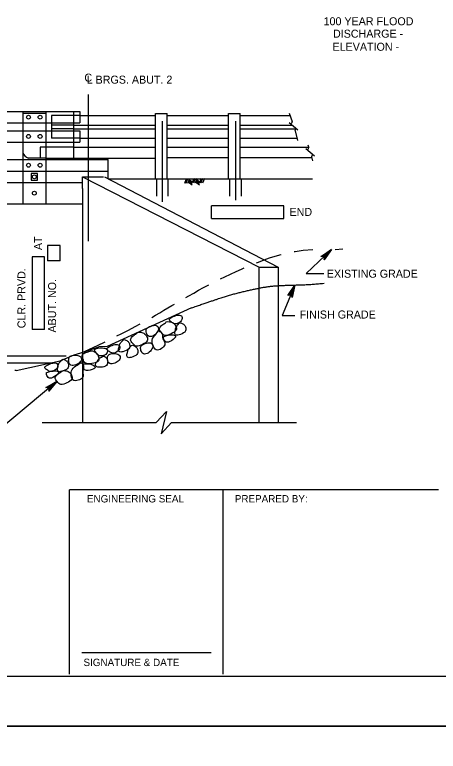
# Model space of a CAD drawing. Extents: x -8 to 75, y -110 to 0.
# Drawn here: x 11.66 to 18.01, y -44.38 to -33.33 of the extents above; entities that cross this region are included whole.
import ezdxf

# ---------------------------------------------------------------- set-up
doc = ezdxf.new("R2010")
doc.units = 0
for name, color, linetype in [('1', 7, 'Continuous'), ('10', 7, 'Continuous'), ('3', 7, 'Continuous'), ('4', 7, 'Continuous'), ('63', 7, 'Continuous'), ('8', 7, 'Continuous')]:
    doc.layers.add(name, color=color, linetype=linetype)

# ---------------------------------------------------------------- blocks, each defined once
blk = doc.blocks.new('F10000')
at = {"layer": '63'}
blk.add_lwpolyline([(-0.03125, -0.03125), (0.03125, -0.03125), (0.03125, 0.03125), (-0.03125, 0.03125)], close=True, dxfattribs=at)

msp = doc.modelspace()

# ---------------------------------------------------------------- linework, layer by layer
at = {"layer": '1'}
msp.add_lwpolyline([(1.75, -43.25), (33.25, -43.25), (33.25, -22.75), (1.75, -22.75)], close=True, dxfattribs=at)
at = {"layer": '3'}
for p, q in [((5.56, -34.783), (12.637, -34.783)), ((11.781, -34.783), (11.781, -36.167)), ((11.781, -34.812), (12.127, -34.812)), ((12.127, -34.783), (12.127, -36.167)), ((12.637, -34.844), (12.213, -34.844)), ((12.213, -34.844), (12.213, -35.184)), ((12.542, -34.783), (12.542, -34.956)), ((12.637, -34.783), (12.637, -34.956)), ((12.637, -34.844), (13.77, -34.844)), ((13.77, -34.814), (13.943, -34.814)), ((13.77, -35.792), (13.77, -34.814)), ((13.943, -35.792), (13.943, -34.814)), ((13.943, -34.846), (14.866, -34.846)), ((14.866, -34.817), (15.039, -34.817)), ((14.866, -35.792), (14.866, -34.817)), ((15.039, -35.792), (15.039, -34.817)), ((15.039, -34.846), (15.787, -34.846)), ((15.775, -34.809), (15.816, -34.936)), ((10.223, -34.956), (11.781, -34.956)), ((11.781, -34.956), (12.127, -34.956)), ((12.127, -34.956), (12.637, -34.956)), ((12.542, -34.99), (12.213, -34.99)), ((12.542, -34.956), (12.542, -35.072)), ((12.542, -34.99), (13.77, -34.99)), ((13.871, -34.927), (13.871, -36.138)), ((13.943, -34.99), (14.866, -34.99)), ((14.967, -34.927), (14.967, -36.113)), ((15.039, -34.99), (15.82, -34.99)), ((15.773, -34.951), (15.904, -35.061)), ((10.223, -35.072), (11.781, -35.072)), ((11.781, -35.072), (12.127, -35.072)), ((12.127, -35.072), (12.637, -35.072)), ((12.542, -35.042), (12.213, -35.042)), ((12.542, -35.042), (13.77, -35.042)), ((12.542, -35.072), (12.542, -35.245)), ((12.637, -35.072), (12.637, -35.245)), ((13.943, -35.042), (14.866, -35.042)), ((15.039, -35.042), (15.882, -35.042)), ((15.861, -35.074), (15.897, -35.219)), ((12.637, -35.184), (12.213, -35.184)), ((12.637, -35.184), (13.77, -35.184)), ((13.943, -35.184), (14.866, -35.184)), ((15.039, -35.184), (15.888, -35.184)), ((10.223, -35.245), (11.781, -35.245)), ((11.781, -35.245), (12.127, -35.245)), ((12.542, -35.32), (12.04, -35.32)), ((12.04, -35.32), (12.04, -35.483)), ((12.127, -35.245), (12.637, -35.245)), ((12.542, -35.245), (12.542, -35.483)), ((12.542, -35.32), (13.77, -35.32)), ((13.943, -35.32), (14.866, -35.32)), ((15.039, -35.32), (16.064, -35.32)), ((16.053, -35.285), (16.066, -35.324)), ((16.023, -35.34), (16.154, -35.45)), ((10.223, -35.504), (11.781, -35.504)), ((11.781, -35.504), (12.127, -35.504)), ((12.127, -35.483), (11.863, -35.483)), ((12.126, -35.483), (13.77, -35.483)), ((12.127, -35.504), (13.059, -35.504)), ((13.059, -35.792), (13.059, -35.504)), ((14.866, -35.478), (13.943, -35.478)), ((16.114, -35.478), (15.039, -35.478)), ((16.11, -35.463), (16.125, -35.523)), ((10.223, -35.677), (11.781, -35.677)), ((11.781, -35.677), (12.127, -35.677)), ((12.127, -35.677), (13.059, -35.677)), ((12.675, -35.764), (15.323, -37.119)), ((12.675, -35.937), (12.675, -35.764)), ((12.675, -35.764), (12.992, -35.764)), ((13.003, -35.764), (15.608, -37.119)), ((10.223, -35.85), (11.781, -35.85)), ((11.781, -35.85), (12.127, -35.85)), ((12.127, -35.85), (12.675, -35.85)), ((13.059, -35.792), (16.125, -35.792)), ((13.784, -35.792), (13.784, -36.052)), ((13.957, -35.792), (13.957, -36.052)), ((14.229, -35.792), (14.203, -35.863)), ((14.251, -35.792), (14.225, -35.862)), ((14.277, -35.792), (14.25, -35.862)), ((14.258, -35.84), (14.318, -35.882)), ((14.265, -35.822), (14.317, -35.858)), ((14.271, -35.805), (14.323, -35.841)), ((14.342, -35.792), (14.316, -35.861)), ((14.364, -35.791), (14.338, -35.86)), ((14.389, -35.791), (14.363, -35.86)), ((14.371, -35.84), (14.431, -35.882)), ((14.377, -35.822), (14.429, -35.858)), ((14.384, -35.805), (14.435, -35.841)), ((14.454, -35.791), (14.428, -35.86)), ((14.476, -35.791), (14.45, -35.86)), ((14.502, -35.791), (14.476, -35.86)), ((14.88, -35.792), (14.88, -36.052)), ((15.053, -35.792), (15.053, -36.052)), ((12.675, -35.937), (12.675, -38.397)), ((5.523, -36.167), (12.675, -36.167)), ((16.409, -36.855), (16.03, -37.212)), ((15.323, -37.119), (15.608, -37.119)), ((15.323, -37.433), (15.323, -37.119)), ((15.608, -37.119), (15.608, -37.397)), ((16.03, -37.212), (16.294, -37.212)), ((15.608, -37.397), (15.608, -39.448)), ((15.859, -37.386), (15.668, -37.842)), ((15.323, -39.448), (15.323, -37.433)), ((14.309, -37.728), (13.045, -38.308)), ((15.668, -37.842), (15.859, -37.842)), ((13.045, -38.308), (12.919, -38.311)), ((12.675, -38.397), (12.675, -39.448)), ((5.777, -38.552), (12.207, -38.552)), ((13.779, -39.448), (13.933, -39.281)), ((13.933, -39.281), (13.856, -39.614)), ((12.072, -39.448), (13.779, -39.448)), ((13.856, -39.614), (14.01, -39.448)), ((14.01, -39.448), (15.883, -39.448))]:
    msp.add_line(p, q, dxfattribs=at)
for points in [[(16.307, -36.924), (16.334, -36.952), (16.407, -36.857)], [(15.795, -37.488), (15.831, -37.503), (15.859, -37.386)]]:
    msp.add_lwpolyline(points, close=True, dxfattribs=at)
for centre in [(11.867, -34.87), (12.04, -34.87), (11.867, -35.158), (12.04, -35.158), (11.867, -35.59), (12.04, -35.59), (11.954, -35.763), (11.954, -36.008)]:
    msp.add_circle(centre, 0.0288, dxfattribs=at)
for centre, radius, start, end in [((15.796, -34.942), 0.0213, 227.8504, 17.8504), ((15.881, -35.07), 0.0213, 49.9832, 192.5218), ((15.882, -35.07), 0.0213, 49.9832, 49.9972), ((16.045, -35.331), 0.0213, 227.8504, 17.8504), ((11.896, -35.37), 0.118, 193.1962, 254.1617), ((16.131, -35.458), 0.0213, 49.9832, 192.5218), ((16.131, -35.458), 0.0213, 49.9832, 49.9972), ((11.66, -39.127), 0.459, 87.4213, 90)]:
    msp.add_arc(centre, radius, start, end, dxfattribs=at)
for points, degree in [([(14.309, -37.728), (14.62, -37.621), (14.906, -37.528), (15.192, -37.458), (15.462, -37.405), (15.716, -37.388), (16.057, -37.382), (16.296, -37.359)], 2), ([(13.983, -37.921), (13.993, -37.932), (14.028, -37.954), (14.072, -37.98), (14.151, -37.942), (14.182, -37.865), (14.138, -37.829), (14.057, -37.846), (13.97, -37.892), (13.974, -37.911), (13.983, -37.921)], 3), ([(13.927, -37.944), (13.925, -37.947), (13.912, -37.959), (13.848, -37.995), (13.816, -38.053), (13.856, -38.094), (13.904, -38.16), (14.008, -38.12), (14.096, -38.063), (14.074, -37.999), (14.043, -37.954), (13.979, -37.93), (13.925, -37.938), (13.929, -37.94), (13.927, -37.944)], 3), ([(14.068, -38.061), (14.066, -38.073), (14.054, -38.088), (14.06, -38.137), (14.113, -38.144), (14.229, -38.094), (14.225, -38.023), (14.205, -37.98), (14.154, -37.951), (14.128, -37.95), (14.116, -37.974), (14.069, -38.016), (14.071, -38.049), (14.068, -38.061)], 3), ([(13.638, -38.037), (13.627, -38.052), (13.628, -38.086), (13.653, -38.159), (13.727, -38.164), (13.797, -38.099), (13.825, -38.034), (13.786, -37.98), (13.695, -37.997), (13.649, -38.022), (13.638, -38.037)], 3), ([(13.811, -38.076), (13.805, -38.08), (13.801, -38.098), (13.71, -38.19), (13.72, -38.279), (13.776, -38.382), (13.864, -38.342), (13.921, -38.281), (13.902, -38.227), (13.872, -38.186), (13.877, -38.112), (13.834, -38.076), (13.816, -38.072), (13.811, -38.076)], 3), ([(13.496, -38.103), (13.494, -38.106), (13.48, -38.118), (13.417, -38.154), (13.385, -38.212), (13.425, -38.254), (13.473, -38.319), (13.577, -38.279), (13.665, -38.222), (13.643, -38.158), (13.612, -38.113), (13.548, -38.089), (13.494, -38.097), (13.498, -38.1), (13.496, -38.103)], 3), ([(13.909, -38.153), (13.892, -38.158), (13.88, -38.163), (13.908, -38.245), (13.977, -38.252), (14.102, -38.153), (14.028, -38.132), (13.98, -38.128), (13.925, -38.147), (13.909, -38.153)], 3), ([(13.048, -38.361), (13.058, -38.371), (13.092, -38.393), (13.136, -38.419), (13.216, -38.381), (13.246, -38.304), (13.203, -38.268), (13.122, -38.286), (13.035, -38.331), (13.038, -38.35), (13.048, -38.361)], 3), ([(13.227, -38.313), (13.225, -38.325), (13.213, -38.34), (13.219, -38.389), (13.272, -38.395), (13.388, -38.346), (13.384, -38.275), (13.364, -38.231), (13.313, -38.203), (13.287, -38.202), (13.275, -38.226), (13.229, -38.267), (13.23, -38.301), (13.227, -38.313)], 3), ([(13.35, -38.398), (13.347, -38.41), (13.335, -38.425), (13.341, -38.474), (13.395, -38.48), (13.511, -38.43), (13.507, -38.36), (13.487, -38.316), (13.436, -38.288), (13.41, -38.286), (13.398, -38.311), (13.351, -38.352), (13.353, -38.386), (13.35, -38.398)], 3), ([(13.554, -38.299), (13.543, -38.314), (13.544, -38.348), (13.569, -38.421), (13.643, -38.426), (13.713, -38.361), (13.741, -38.296), (13.702, -38.242), (13.611, -38.259), (13.565, -38.284), (13.554, -38.299)], 3), ([(12.799, -38.374), (12.796, -38.376), (12.78, -38.383), (12.708, -38.397), (12.659, -38.44), (12.684, -38.493), (12.708, -38.57), (12.818, -38.566), (12.921, -38.541), (12.921, -38.474), (12.906, -38.421), (12.853, -38.377), (12.799, -38.368), (12.803, -38.371), (12.799, -38.374)], 3), ([(12.86, -38.371), (12.866, -38.384), (12.891, -38.416), (12.925, -38.455), (13.012, -38.445), (13.066, -38.382), (13.036, -38.333), (12.954, -38.324), (12.857, -38.339), (12.854, -38.358), (12.86, -38.371)], 3), ([(13.073, -38.429), (13.057, -38.439), (13.048, -38.471), (13.048, -38.548), (13.116, -38.577), (13.203, -38.539), (13.251, -38.486), (13.231, -38.423), (13.14, -38.409), (13.088, -38.418), (13.073, -38.429)], 3), ([(12.31, -38.608), (12.307, -38.62), (12.295, -38.635), (12.301, -38.684), (12.355, -38.69), (12.471, -38.64), (12.467, -38.57), (12.447, -38.526), (12.396, -38.498), (12.37, -38.497), (12.358, -38.521), (12.311, -38.562), (12.313, -38.596), (12.31, -38.608)], 3), ([(12.492, -38.453), (12.477, -38.463), (12.467, -38.495), (12.467, -38.573), (12.535, -38.602), (12.622, -38.563), (12.67, -38.51), (12.651, -38.447), (12.559, -38.433), (12.507, -38.442), (12.492, -38.453)], 3), ([(12.895, -38.531), (12.888, -38.541), (12.872, -38.551), (12.862, -38.599), (12.911, -38.623), (13.036, -38.614), (13.056, -38.546), (13.051, -38.498), (13.012, -38.455), (12.988, -38.445), (12.968, -38.464), (12.911, -38.488), (12.901, -38.52), (12.895, -38.531)], 3), ([(12.118, -38.637), (12.128, -38.647), (12.162, -38.669), (12.207, -38.695), (12.286, -38.658), (12.316, -38.581), (12.273, -38.544), (12.192, -38.562), (12.105, -38.608), (12.108, -38.627), (12.118, -38.637)], 3), ([(12.65, -38.551), (12.644, -38.552), (12.633, -38.568), (12.518, -38.626), (12.499, -38.713), (12.518, -38.829), (12.614, -38.819), (12.687, -38.781), (12.687, -38.723), (12.672, -38.675), (12.701, -38.607), (12.672, -38.559), (12.656, -38.549), (12.65, -38.551)], 3), ([(12.714, -38.565), (12.696, -38.565), (12.684, -38.565), (12.684, -38.652), (12.746, -38.681), (12.896, -38.628), (12.834, -38.585), (12.79, -38.565), (12.732, -38.565), (12.714, -38.565)], 3), ([(12.156, -38.692), (12.139, -38.697), (12.127, -38.702), (12.155, -38.784), (12.224, -38.791), (12.348, -38.692), (12.275, -38.671), (12.227, -38.667), (12.172, -38.686), (12.156, -38.692)], 3), ([(12.365, -38.679), (12.363, -38.682), (12.349, -38.694), (12.286, -38.73), (12.254, -38.788), (12.294, -38.829), (12.342, -38.895), (12.445, -38.855), (12.534, -38.798), (12.512, -38.734), (12.481, -38.689), (12.417, -38.665), (12.363, -38.673), (12.367, -38.675), (12.365, -38.679)], 3)]:
    msp.add_open_spline(points, degree=degree, dxfattribs=at)
at = {"layer": '4'}
for p, q in [((12.761, -34.529), (12.761, -36.727)), ((15.694, -36.201), (14.608, -36.201)), ((14.608, -36.389), (14.608, -36.201)), ((15.694, -36.389), (15.694, -36.201)), ((14.608, -36.389), (15.694, -36.389)), ((12.153, -36.794), (12.153, -37.024)), ((12.341, -36.794), (12.153, -36.794)), ((12.341, -37.024), (12.341, -36.794)), ((11.919, -36.964), (11.919, -38.05)), ((12.107, -36.964), (11.919, -36.964)), ((12.107, -38.05), (12.107, -36.964)), ((12.341, -37.024), (12.153, -37.024)), ((12.107, -38.05), (11.919, -38.05)), ((11.199, -38.446), (12.432, -38.446)), ((12.293, -38.83), (11.227, -39.719)), ((12.483, -43.22), (12.483, -40.456)), ((18.011, -40.456), (12.483, -40.456)), ((14.786, -43.22), (14.786, -40.456)), ((14.602, -42.897), (12.667, -42.897))]:
    msp.add_line(p, q, dxfattribs=at)
for points in [[(16.409, -36.855), (16.297, -37.008), (16.301, -36.991), (16.298, -36.977), (16.291, -36.966), (16.281, -36.959), (16.267, -36.955), (16.25, -36.957), (16.409, -36.855), (16.267, -36.955), (16.281, -36.959), (16.409, -36.855), (16.291, -36.966), (16.298, -36.977), (16.409, -36.855), (16.301, -36.991)], [(15.859, -37.386), (15.819, -37.572), (15.815, -37.555), (15.807, -37.543), (15.796, -37.536), (15.784, -37.533), (15.769, -37.535), (15.755, -37.545), (15.859, -37.386), (15.769, -37.535), (15.784, -37.533), (15.859, -37.386), (15.796, -37.536), (15.807, -37.543), (15.859, -37.386), (15.815, -37.555)], [(11.681, -38.669), (12.341, -38.522), (12.551, -38.432), (12.702, -38.389), (12.919, -38.311)], [(12.293, -38.83), (12.172, -38.976), (12.177, -38.96), (12.175, -38.945), (12.168, -38.934), (12.159, -38.926), (12.145, -38.921), (12.127, -38.923), (12.293, -38.83), (12.145, -38.921), (12.159, -38.926), (12.293, -38.83), (12.168, -38.934), (12.175, -38.945), (12.293, -38.83), (12.177, -38.96)]]:
    msp.add_lwpolyline(points, dxfattribs=at)
msp.add_lwpolyline([(12.19, -38.891), (12.215, -38.921), (12.293, -38.83)], close=True, dxfattribs=at)
at = {"layer": '63'}
for points in [[(0, -44), (34, -44), (34, -22), (0, -22)], [(0, -66), (34, -66), (34, -44), (0, -44)]]:
    msp.add_lwpolyline(points, close=True, dxfattribs=at)
at = {"layer": '8'}
for p, q in [((15.861, -36.883), (15.985, -36.865)), ((15.985, -36.865), (16.126, -36.851)), ((16.465, -36.851), (16.578, -36.844)), ((15.396, -37.01), (15.479, -36.98)), ((15.479, -36.98), (15.564, -36.953)), ((15.564, -36.953), (15.654, -36.927)), ((15.654, -36.927), (15.655, -36.926)), ((15.848, -36.885), (15.861, -36.883)), ((15.283, -37.054), (15.313, -37.042)), ((15.313, -37.042), (15.396, -37.01)), ((14.893, -37.222), (14.977, -37.184)), ((14.977, -37.184), (15.061, -37.147)), ((15.061, -37.147), (15.101, -37.129)), ((14.744, -37.294), (14.81, -37.261)), ((14.81, -37.261), (14.893, -37.222)), ((14.415, -37.465), (14.491, -37.424)), ((14.491, -37.424), (14.568, -37.383)), ((14.271, -37.546), (14.342, -37.506)), ((14.342, -37.506), (14.415, -37.465)), ((14.224, -37.573), (14.271, -37.546)), ((13.897, -37.765), (13.957, -37.73)), ((13.957, -37.73), (14.016, -37.695)), ((14.016, -37.695), (14.054, -37.672)), ((13.714, -37.871), (13.772, -37.838)), ((13.772, -37.838), (13.836, -37.801)), ((13.836, -37.801), (13.897, -37.765)), ((13.464, -38.009), (13.542, -37.967)), ((13.257, -38.117), (13.367, -38.061)), ((13.367, -38.061), (13.464, -38.009)), ((13.192, -38.149), (13.257, -38.117)), ((12.836, -38.32), (12.993, -38.246)), ((12.993, -38.246), (13.016, -38.235)), ((12.659, -38.401), (12.836, -38.32))]:
    msp.add_line(p, q, dxfattribs=at)

# ---------------------------------------------------------------- block references
at = {"layer": '3', "xscale": 1.5875015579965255, "yscale": 1.5875015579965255}
msp.add_blockref('F10000', (11.954, -35.763), dxfattribs=at)

# ---------------------------------------------------------------- texts
at = {"layer": '10'}
for s, p in [('ENGINEERING SEAL', (12.742, -40.645)), ('PREPARED BY:', (14.958, -40.645)), ('SIGNATURE & DATE', (12.69, -43.098))]:
    msp.add_text(s, height=0.11054, dxfattribs=at).set_placement(p)
at = {"layer": '4'}
for s, p in [('100 YEAR FLOOD', (16.289, -33.492)), ('   DISCHARGE - ', (16.296, -33.678)), ('   ELEVATION - ', (16.289, -33.874)), ('C', (12.704, -34.337)), ('L BRGS. ABUT. 2', (12.738, -34.367)), ('END', (15.778, -36.35)), ('EXISTING GRADE', (16.337, -37.276)), ('FINISH GRADE', (15.93, -37.888))]:
    msp.add_text(s, height=0.12, dxfattribs=at).set_placement(p)
for s, p in [('AT', (12.069, -36.862)), ('CLR. PRVD.', (11.821, -38.034)), ('ABUT. NO. ', (12.28, -38.098))]:
    msp.add_text(s, height=0.12, rotation=90, dxfattribs=at).set_placement(p)

doc.saveas('drawing.dxf')
